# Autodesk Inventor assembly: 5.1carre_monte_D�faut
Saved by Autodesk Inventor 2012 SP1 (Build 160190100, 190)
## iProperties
Created: 2011-01
Part Number: 5.1carre_monte_D�faut
Document SubType Name: Assembly
Designer: eric
Mass: 25.3714 g
Surface Area: 253.737 cm^2
Volume: 25.3714 cm^3
Density: 1 g/cm^3
Author: eric
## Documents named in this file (9)
- D:\Cours\Inventor salle SI\chariot_de_golf_2008\chariot_de_golf_trolem\5.1carre_monte_Defaut.iam
- D:\Cours\Inventor salle SI\chariot_de_golf_2008\chariot_de_golf_trolem\bead103_Defaut.ipt
- D:\Cours\Inventor salle SI\chariot_de_golf_2008\chariot_de_golf_trolem\5.1entretoise_Defaut.ipt
- D:\Cours\Inventor salle SI\chariot_de_golf_2008\chariot_de_golf_trolem\5.1plaque_Defaut.ipt
- D:\Cours\Inventor salle SI\chariot_de_golf_2008\chariot_de_golf_trolem\5.1VisH M10-60_Defaut.ipt
- D:\Cours\Inventor salle SI\chariot_de_golf_2008\chariot_de_golf_trolem\5.1TubeCarre25x25x1.5_Defaut.ipt
- D:\Cours\Inventor salle SI\chariot_de_golf_2008\chariot_de_golf_trolem\bead106_Defaut.ipt
- D:\Cours\Inventor salle SI\chariot_de_golf_2008\chariot_de_golf_trolem\bead104_Defaut.ipt
- D:\Cours\Inventor salle SI\chariot_de_golf_2008\chariot_de_golf_trolem\bead105_Defaut.ipt
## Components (8 placed, 8 different names)
1. bead103_Defaut:1
2. 5.1entretoise_Defaut:1
3. 5.1plaque_Defaut:1
4. 5.1VisH M10-60_Defaut:1
5. 5.1TubeCarre25x25x1.5_Defaut:1
6. bead106_Defaut:1
7. bead104_Defaut:1
8. bead105_Defaut:1
